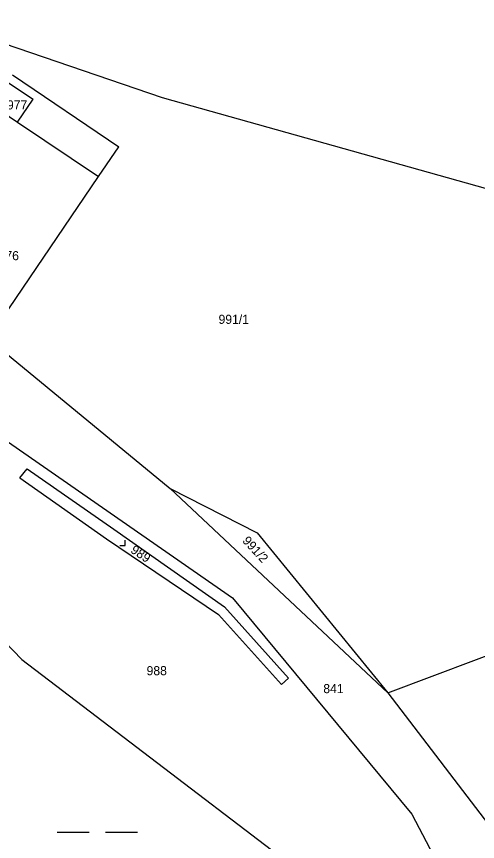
# Model space of a CAD drawing. Extents: x -779596 to -776743, y -1030330 to -1024513.
# Drawn here: x -777364.4 to -777278.3, y -1025778.4 to -1025624.2 of the extents above; entities that cross this region are included whole.
import ezdxf

# ---------------------------------------------------------------- set-up
doc = ezdxf.new("R2010")
doc.units = 0
for name, color, linetype in [('hranice parcel', 7, 'Continuous'), ('hranice vnitřní', 7, 'Continuous'), ('kultura', 7, 'Continuous'), ('č_ parcel šipka', 7, 'Continuous'), ('č_pacel stav_', 7, 'Continuous'), ('č_parcel poz_', 7, 'Continuous')]:
    doc.layers.add(name, color=color, linetype=linetype)

msp = doc.modelspace()

# ---------------------------------------------------------------- linework, layer by layer
at = {"layer": 'hranice parcel'}
for points in [[(-777381.53, -1025624.16), (-777337.14, -1025639.31)], [(-777365.13, -1025635.08), (-777345.27, -1025648.53)], [(-777337.14, -1025639.31), (-777274.83, -1025656.83)], [(-777368.93, -1025640.72), (-777364.16, -1025643.91)], [(-777364.16, -1025643.91), (-777349.04, -1025654.07)], [(-777349.04, -1025654.07), (-777345.27, -1025648.53)], [(-777369.66, -1025684.42), (-777349.04, -1025654.07)], [(-777369.66, -1025684.42), (-777335.68, -1025712.37)], [(-777417.05, -1025688.63), (-777363.38, -1025744.36)], [(-777376.36, -1025696.48), (-777324.06, -1025732.82)], [(-777363.76, -1025710.38), (-777362.41, -1025708.7)], [(-777362.41, -1025708.7), (-777346.2, -1025719.98)], [(-777363.76, -1025710.38), (-777347.55, -1025721.82)], [(-777335.68, -1025712.37), (-777295.02, -1025750.59)], [(-777335.68, -1025712.37), (-777319.41, -1025720.69)], [(-777346.2, -1025719.98), (-777325.54, -1025734.5)], [(-777347.55, -1025721.82), (-777326.66, -1025735.98)], [(-777319.41, -1025720.69), (-777295.02, -1025750.59)], [(-777324.06, -1025732.82), (-777290.55, -1025773.29)], [(-777326.66, -1025735.98), (-777314.85, -1025749.02)], [(-777325.54, -1025734.5), (-777313.6, -1025747.86)], [(-777295.02, -1025750.59), (-777270.15, -1025741.27)], [(-777363.38, -1025744.36), (-777291.35, -1025799.33)], [(-777314.85, -1025749.02), (-777313.6, -1025747.86)], [(-777295.02, -1025750.59), (-777274.62, -1025777.35)], [(-777290.55, -1025773.29), (-777283.11, -1025787.41)]]:
    msp.add_lwpolyline(points, dxfattribs=at)
at = {"layer": 'hranice vnitřní'}
for points in [[(-777366.07, -1025636.44), (-777361.29, -1025639.64)], [(-777364.16, -1025643.91), (-777361.29, -1025639.64)]]:
    msp.add_lwpolyline(points, dxfattribs=at)
at = {"layer": 'kultura'}
for points in [[(-777345.05, -1025723.07), (-777344.05, -1025723.07), (-777344.05, -1025722.07)], [(-777356.78, -1025776.64), (-777350.78, -1025776.64)], [(-777347.78, -1025776.64), (-777341.78, -1025776.64)]]:
    msp.add_lwpolyline(points, dxfattribs=at)

# ---------------------------------------------------------------- texts
at = {"layer": 'č_ parcel šipka'}
msp.add_text('841', height=1.7, dxfattribs=at).set_placement((-777307.07, -1025750.66))
at = {"layer": 'č_pacel stav_'}
msp.add_text('977', height=1.7, dxfattribs=at).set_placement((-777366.16, -1025641.53))
msp.add_text('989', height=1.7, rotation=326.30259, dxfattribs=at).set_placement((-777343.213, -1025724.255))
at = {"layer": 'č_parcel poz_'}
for s, p in [('976', (-777367.72, -1025669.72)), ('991/1', (-777326.64, -1025681.62)), ('988', (-777340.08, -1025747.31))]:
    msp.add_text(s, height=1.7, dxfattribs=at).set_placement(p)
msp.add_text('991/2', height=1.7, rotation=312.60249, dxfattribs=at).set_placement((-777322.298, -1025722.261))

doc.saveas('drawing.dxf')
